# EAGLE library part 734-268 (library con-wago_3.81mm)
Serie 734, Stiftleiste (für Leiterplatten) Einlötstift abgewinkelt 1 x 1 mm / Series 734, Male header (for PCBs) Angled solder pin 1 x 1 mm Polzahl / Pole No.: 8 Rastermaß / Pitch: 3.81 mm Bemessungsspannung / Rated Voltage: 160 V Nennstrom / Nominal Current: 10 A Lötstiftlänge: / Solder Pin Length: 3.8 mm Farbe / Color: orange / orange Stand: 01.01.2012. Die jeweils aktuellen Daten zu diesem Artikel finden Sie in unserem Produktkatalog, den Sie unter www.wago.com einsehen können. As of: 01/01/2012. Please find the newest data for this article in our product catalogue, which can be viewed under www.wago.com.
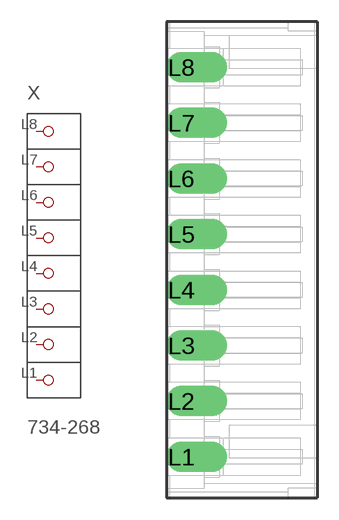
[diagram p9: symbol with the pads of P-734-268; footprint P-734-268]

Designator prefix X

## 734-268  [P-734-268]
L1  P1
L2  P2
L3  P3
L4  P4
L5  P5
L6  P6
L7  P7
L8  P8

## Footprint P-734-268 (pad centres in mm)
drill 1.4 pad 2 offset: L1 -4.15,-13.485; L2 -4.15,-9.675; L3 -4.15,-5.865; L4 -4.15,-2.055; L5 -4.15,1.755; L6 -4.15,5.565; L7 -4.15,9.375; L8 -4.15,13.185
